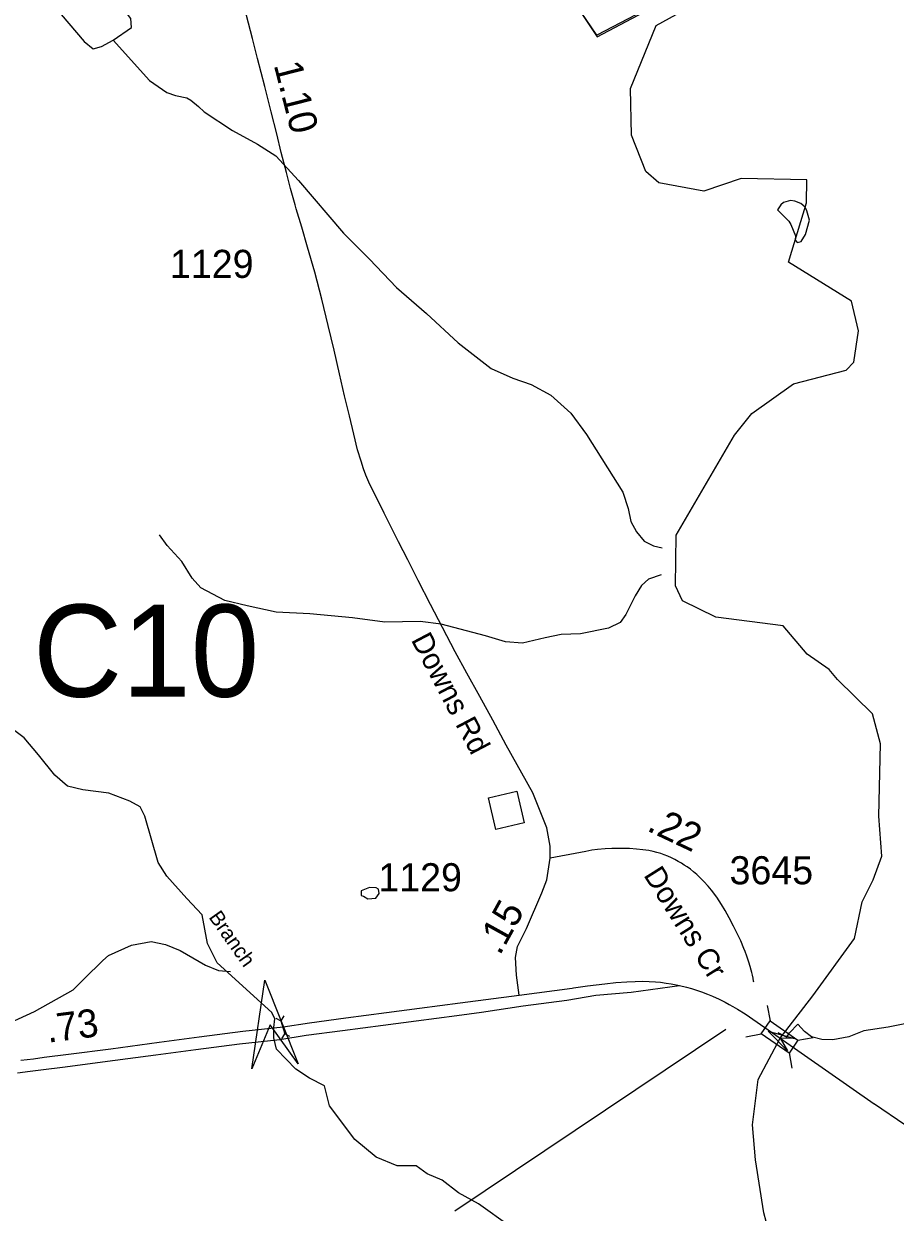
# Model space of a CAD drawing. Extents: x 1383679 to 1536984, y 460658 to 651027.
# Drawn here: x 1428508 to 1432384, y 492583 to 497871 of the extents above; entities that cross this region are included whole.
import ezdxf

# ---------------------------------------------------------------- set-up
doc = ezdxf.new("R2010")
doc.units = 0
for name, color, linetype in [('Default', 7, 'Continuous'), ('Exist Boundary Political City Limit New', 7, 'Continuous'), ('Exist Cultural Warehouse Building Footprint', 7, 'Continuous'), ('Exist Hydrographic Creek Single Shore', 7, 'Continuous'), ('Exist Hydrographic Creek Single Shore Label', 7, 'Continuous'), ('Exist Hydrographic Misc Water Feature', 7, 'Continuous'), ('Exist Road Primary NC Attributed', 7, 'Continuous'), ('Exist Road Primary NC Divided Attributed', 7, 'Continuous'), ('Exist Road Primary NC Service Mileage Hundredths English Label', 7, 'Continuous'), ('Exist Road Primary NC Structure Standard Bridge CELL', 7, 'Continuous'), ('Exist Road Secondary Mileage Hundredths English Label', 7, 'Continuous'), ('Exist Road Secondary Structure Culvert Attributed CELL', 7, 'Continuous'), ('Exist Road Secondary Structure Culvert CELL', 7, 'Continuous'), ('Exist Road Secondary Structure Culvert Number Label', 7, 'Continuous'), ('Exist Road Secondary Structure Standard Bridge Attributed CELL', 7, 'Continuous'), ('Exist Road Secondary Type 51 Attributed', 7, 'Continuous'), ('Exist Road Secondary Type 51 Label', 7, 'Continuous'), ('Exist Road Secondary Type 51 Number Label', 7, 'Continuous'), ('Map Preparation Boundary City Limit Buffer Line', 7, 'Continuous'), ('Prop Road TIP Projects U Label', 7, 'Continuous')]:
    doc.layers.add(name, color=color, linetype=linetype)

msp = doc.modelspace()

# ---------------------------------------------------------------- linework, layer by layer
at = {"layer": 'Default'}
msp.add_line((1431862.4, 493382.6), (1431901.8, 493361.5), dxfattribs=at)
msp.add_lwpolyline([(1431264.4, 497929.3), (1431056.9, 497819.8), (1430898.1, 498054.8)], dxfattribs=at)
at = {"layer": 'Exist Boundary Political City Limit New'}
for points in [[(1431264.4, 497929.3), (1431056.9, 497819.8), (1430898.1, 498054.8)], [(1430898.1, 498054.8), (1431058.5, 497813.6), (1431266, 497923.2)]]:
    msp.add_lwpolyline(points, dxfattribs=at)
at = {"layer": 'Exist Cultural Warehouse Building Footprint'}
msp.add_lwpolyline([(1430574.6, 494427.7), (1430701, 494457.2), (1430734, 494315.3), (1430607.7, 494285.9), (1430574.6, 494427.7)], dxfattribs=at)
at = {"layer": 'Exist Hydrographic Creek Single Shore'}
for points in [[(1432128, 494953), (1432090.2, 494998.4), (1431992.2, 495066), (1431886.2, 495192.9), (1431586.2, 495231.7), (1431438.3, 495303.6), (1431406.3, 495369.9), (1431410.3, 495596.3), (1431669.3, 496040.8), (1431746.3, 496137.7), (1431932.2, 496268.5), (1432166.2, 496329.5), (1432200.2, 496364.9), (1432220.2, 496505.7), (1432189.3, 496637.6), (1431909.3, 496810.6), (1431989.3, 497074.8), (1431991.2, 497176.6), (1431699.2, 497182.5), (1431532.3, 497126.7), (1431332.3, 497163.6), (1431275.3, 497214), (1431211.3, 497376.1), (1431207.3, 497583), (1431321.3, 497863), (1431498.3, 497961.2)], [(1431363.3, 491653.7), (1431867.1, 491773.5), (1431951.4, 491791.3), (1431993.6, 491822.4), (1432031.3, 491851.2), (1432031.3, 491931.1), (1432024.7, 492024.3), (1431968.2, 492141.9), (1431889.3, 492308.4), (1431841.6, 492426), (1431799.4, 492581.3), (1431762.8, 492816.6), (1431749.5, 492971.9), (1431774.4, 493174.4), (1431871.7, 493357.8), (1432018, 493546.7), (1432202.2, 493801.9), (1432237.7, 493963.9), (1432286.5, 494061.6), (1432324.2, 494168.1), (1432310.9, 494345.6), (1432318.7, 494667.4), (1432283.2, 494800.6), (1432128, 494953)], [(1430670.9, 492519.2), (1430531.1, 492621.3), (1430442.4, 492670.1), (1430369.1, 492725.6), (1430302.5, 492754.4), (1430253.7, 492789.9), (1430169.4, 492789.9), (1430076.2, 492827.7), (1429980.8, 492907.6), (1429868.2, 493057.2), (1429845.4, 493145), (1429778.8, 493180.5), (1429718.8, 493219.6), (1429632.1, 493309.4), (1429621.2, 493359.2), (1429621.2, 493404.7), (1429624.6, 493443.5), (1429611.1, 493472.6), (1429368.2, 493693.2), (1429326.1, 493779.7), (1429301.7, 493906.2), (1429232.9, 493979.4), (1429145.2, 494079.3), (1429106.4, 494139.2), (1429046.5, 494345.6), (1429026.5, 494387.8), (1428979.9, 494412.2), (1428886.7, 494447.7), (1428771.3, 494463.2), (1428702.5, 494478.8), (1428647, 494527.6), (1428573.8, 494618.6), (1428510.7, 494693.7), (1428403, 494774.9)]]:
    msp.add_lwpolyline(points, dxfattribs=at)
at = {"layer": 'Exist Hydrographic Misc Water Feature'}
for points in [[(1428906.5, 497798.4), (1428987.6, 497854.2), (1428984.4, 497894.4), (1428959, 497926.9), (1428899.4, 497947.9), (1428800.4, 497999.9), (1428747, 498035.5), (1428733.2, 498041.5), (1428683.2, 498042.5), (1428655.2, 498043.1)], [(1428655.2, 498043.1), (1428655.9, 497976.6), (1428674.6, 497912.2), (1428776.3, 497792.8), (1428817.7, 497759.9), (1428853.9, 497770.7), (1428906.5, 497798.4)], [(1428906.5, 497798.4), (1429067, 497618.7), (1429144, 497565.4), (1429183.8, 497552.4), (1429233.6, 497541.5), (1429251.5, 497531.3), (1429284.9, 497502.7), (1429310.4, 497480), (1429436.9, 497397.1), (1429547.8, 497335), (1429628.8, 497283.2), (1429730.7, 497173.7), (1429930.2, 496939.9), (1430046, 496823.5), (1430165.6, 496697.2), (1430299.4, 496582.1), (1430440.9, 496451.2), (1430586.8, 496336.7), (1430684, 496294.5), (1430765.5, 496266.6), (1430852.6, 496218.9), (1430941, 496139.2), (1431011.2, 496044.2), (1431172.2, 495786.6), (1431196.9, 495714.7), (1431207.8, 495656.2), (1431232.9, 495611.4), (1431268.1, 495568.8), (1431309.7, 495548.3), (1431347.5, 495539.3)], [(1431861.1, 497043.8), (1431910.2, 496992.8), (1431919.9, 496978.6), (1431940.9, 496928.1), (1431938.6, 496910.1), (1431948.3, 496898.5), (1431966.4, 496902.2), (1431985, 496933.8), (1432002.3, 496997.5), (1431991.1, 497039.6), (1431983.4, 497055.3), (1431963.7, 497072.1), (1431937.9, 497082.5), (1431918, 497084.5), (1431887.8, 497075.3), (1431875.6, 497065.7), (1431861.1, 497043.8)], [(1431343.2, 495419.6), (1431286.8, 495400.2), (1431256.2, 495371.3), (1431227.3, 495326), (1431185.6, 495242.3), (1431160.9, 495206.7), (1431108.4, 495181.5), (1430983.9, 495156.1), (1430897.8, 495153.7), (1430827.4, 495139.5), (1430726.9, 495115.3), (1430651.1, 495120.9), (1430561.5, 495148.1), (1430364.4, 495200.5), (1430270.6, 495212.3), (1430114.5, 495208.8), (1429970.8, 495228.2), (1429781, 495245.9), (1429631.1, 495253.1), (1429501.6, 495281.1), (1429402, 495305.3), (1429295.1, 495361.5), (1429257.9, 495404.1), (1429211.4, 495478.9), (1429146.7, 495550), (1429111.6, 495596.7)], [(1430045.3, 494027.8), (1430009, 494012.9), (1430008.6, 493992.4), (1430018.7, 493988.9), (1430038.5, 493977.9), (1430074.4, 493981.2), (1430088.9, 494001.4), (1430085.3, 494021.2), (1430075.4, 494027.2), (1430045.3, 494027.8)], [(1433299.2, 493938.4), (1433258.7, 493915.5), (1433190.4, 493900.4), (1433134.2, 493891.7), (1433118.1, 493886.3), (1433065.4, 493852.9), (1432957.5, 493757.4), (1432798.8, 493617.8), (1432650.6, 493514.9), (1432555.5, 493454.5), (1432523.2, 493441.2), (1432352.4, 493406.9), (1432244.1, 493391), (1432177.5, 493364.4), (1432107.1, 493351.1), (1432057.2, 493352.1), (1432011.4, 493363.7), (1431979.9, 493388.1), (1431950.5, 493420.7)], [(1428392.4, 493402.1), (1428555.9, 493476.8), (1428728, 493573.4), (1428776.9, 493622.5), (1428860.5, 493702.9), (1428885, 493726.1), (1428987.9, 493770.9), (1429074.3, 493787.2), (1429138.1, 493775.2), (1429203.6, 493748.4), (1429316.3, 493682.2), (1429373.9, 493658.9), (1429427.8, 493653.7)], [(1431901.8, 493361.5), (1431913.7, 493381.3), (1431950.5, 493420.7)]]:
    msp.add_lwpolyline(points, dxfattribs=at)
at = {"layer": 'Exist Road Primary NC Attributed'}
for points in [[(1431424.8, 493592.1), (1431455.1, 493585.1), (1431477.9, 493578.9), (1431499.5, 493571.7), (1431521.8, 493563.9), (1431549, 493554.1), (1431571.5, 493544.8), (1431600.5, 493530.9), (1431627.3, 493517.8), (1431645.4, 493507.7), (1431661.7, 493499), (1431682.3, 493487.1), (1431716.5, 493465.9), (1431871.7, 493357.8)], [(1431871.7, 493357.8), (1432290.7, 493066), (1432291.7, 493065.3), (1432427.3, 492973.9), (1432846.6, 492676), (1432961.4, 492591.1), (1432968.9, 492585.9), (1433416.4, 492271.8)]]:
    msp.add_lwpolyline(points, dxfattribs=at)
at = {"layer": 'Exist Road Primary NC Divided Attributed'}
for points in [[(1428480.1, 493203.8), (1428536.6, 493210.5), (1428584.3, 493216.8), (1428692.6, 493230.3), (1428880.4, 493254.7), (1429096.4, 493283.7), (1429273.4, 493307.3), (1429468.4, 493332.8), (1429647.5, 493352.5), (1429764.3, 493370.9), (1429925.7, 493392.4), (1430107.1, 493416.2), (1430253.5, 493435.4), (1430434.7, 493459.2), (1430544.4, 493473.5), (1430728.6, 493502.3), (1430923.9, 493526.7), (1431052.6, 493548.9), (1431210.2, 493562.2), (1431424.8, 493592.1)], [(1430710.9, 493548.9), (1430868.4, 493570.1), (1430947, 493580.7), (1430952.5, 493581.4), (1431015.3, 493590), (1431092.5, 493599.8), (1431141.7, 493604.8), (1431189.9, 493608.9), (1431227.6, 493610.4), (1431260.1, 493610.8), (1431289.2, 493610.4), (1431318.6, 493608.6), (1431340.6, 493606.6), (1431365.3, 493603.1), (1431387.7, 493599.4), (1431417.9, 493593.6), (1431424.8, 493592.1)], [(1428494.7, 493259.5), (1428551.1, 493266.2), (1428598.8, 493272.5), (1428707.1, 493286), (1428894.9, 493310.4), (1429110.9, 493339.4), (1429287.9, 493363), (1429482.9, 493388.4), (1429662, 493408.2), (1429778.9, 493426.6), (1429940.2, 493448.1), (1430121.7, 493471.9), (1430268, 493491.1), (1430449.2, 493514.9), (1430710.9, 493548.9)]]:
    msp.add_lwpolyline(points, dxfattribs=at)
at = {"layer": 'Exist Road Primary NC Structure Standard Bridge CELL'}
for p, q in [((1431814.5, 493502.6), (1431827.1, 493434.8)), ((1431719.3, 493364), (1431787.1, 493376.6)), ((1431951.4, 493348.9), (1432019.3, 493361.4)), ((1431912.3, 493292), (1431924.9, 493224.2))]:
    msp.add_line(p, q, dxfattribs=at)
msp.add_lwpolyline([(1431827.1, 493434.8), (1431951.6, 493349.1), (1431911.6, 493291), (1431787.1, 493376.6)], close=True, dxfattribs=at)
at = {"layer": 'Exist Road Secondary Structure Culvert Attributed CELL'}
msp.add_lwpolyline([(1429522.5, 493220.6), (1429581.1, 493616.3), (1429728.2, 493244.3), (1429604, 493417.6)], close=True, dxfattribs=at)
at = {"layer": 'Exist Road Secondary Structure Culvert CELL'}
for p, q in [((1429629.5, 493446.9), (1429652.1, 493435.4)), ((1429664.9, 493457.3), (1429652.1, 493435.4)), ((1429652.1, 493435.4), (1429669.1, 493377.3)), ((1429656.3, 493355.4), (1429669.1, 493377.3)), ((1429691.7, 493365.8), (1429669.1, 493377.3))]:
    msp.add_line(p, q, dxfattribs=at)
at = {"layer": 'Exist Road Secondary Structure Standard Bridge Attributed CELL'}
msp.add_lwpolyline([(1431904.4, 493301.6), (1431819.3, 493388.9), (1431936.6, 493355.9), (1431871.7, 493357.8)], close=True, dxfattribs=at)
at = {"layer": 'Exist Road Secondary Type 51 Attributed'}
for points in [[(1430849.6, 494159.2), (1430849.6, 494212.5), (1430835.2, 494293.5), (1430773, 494449.9), (1430653.9, 494661), (1430594.6, 494773.1), (1430536.2, 494878.5), (1430478.8, 494982.2), (1430427.3, 495077.2), (1430370.4, 495185), (1430317.1, 495288), (1430261.8, 495394.7), (1430215.9, 495486), (1430175.6, 495566.5), (1430130.6, 495655.4), (1430111.1, 495693.8), (1430069.4, 495778.2), (1430048.1, 495821.8), (1430029.7, 495863.5), (1430019.4, 495890.7), (1430008.4, 495924.5), (1429993.2, 495975.5), (1429975.8, 496045.3), (1429956.3, 496126.1), (1429935, 496215.6), (1429913, 496313.7), (1429888.4, 496418.8), (1429862.7, 496529.4), (1429833.8, 496645.4), (1429802.9, 496765.6), (1429770.3, 496876.7), (1429744.5, 496965.7), (1429719.9, 497048.1), (1429715.1, 497066), (1429695.2, 497138.9), (1429676.5, 497209.9), (1429653.8, 497298.4), (1429633.3, 497381.2), (1429608.3, 497480.1), (1429579.8, 497591.8), (1429547.7, 497716.8), (1429525.2, 497805.2), (1429490.5, 497942)], [(1431754.7, 493607.1), (1431754.3, 493610.8), (1431751.9, 493624.9), (1431749.5, 493637.4), (1431746.6, 493649.4), (1431743.3, 493660.6), (1431739.1, 493676), (1431732.8, 493695.4), (1431724.1, 493722.2), (1431716.1, 493743.5), (1431711.3, 493756.2), (1431697.1, 493790.4), (1431681.5, 493823.9), (1431665.1, 493856.7), (1431645.8, 493892.5), (1431628.1, 493925.3), (1431611.4, 493952.3), (1431589.9, 493984.7), (1431566.3, 494016.9), (1431551.5, 494034.7), (1431533.4, 494054.7), (1431518, 494070.4), (1431501.9, 494085.6), (1431487, 494098.5), (1431472.9, 494109.3), (1431459, 494119.5), (1431445.8, 494128), (1431433.9, 494135.7), (1431418.8, 494144.3), (1431403.8, 494152.7), (1431389.3, 494159.7), (1431372.3, 494167.7), (1431356.1, 494174), (1431341.7, 494178.9), (1431323.7, 494184.2), (1431307, 494188.4), (1431288.5, 494192.1), (1431261.2, 494196.3), (1431233.5, 494198.9), (1431202.2, 494201.1), (1431164.6, 494201.8), (1431123.5, 494201.4), (1431093.6, 494199.9), (1431060.1, 494197.1), (1431035.2, 494194), (1431007.5, 494188.8), (1430984.9, 494183.9), (1430849.6, 494159.2)], [(1430710.9, 493548.9), (1430699.8, 493638.8), (1430695.3, 493716.5), (1430704.2, 493765.3), (1430719.8, 493798.6), (1430744.2, 493846.3), (1430813, 494005), (1430835.2, 494062.7), (1430849.6, 494159.2)]]:
    msp.add_lwpolyline(points, dxfattribs=at)
at = {"layer": 'Map Preparation Boundary City Limit Buffer Line'}
for points in [[(1431264.4, 497929.3), (1431056.9, 497819.8), (1430898.1, 498054.8)], [(1430898.1, 498054.8), (1431058.5, 497813.6), (1431266, 497923.2)], [(1431264.4, 497929.3), (1431056.9, 497819.8), (1430898.1, 498054.8)]]:
    msp.add_lwpolyline(points, dxfattribs=at)
at = {"layer": 'Prop Road TIP Projects U Label'}
msp.add_line((1431631.4, 493396.8), (1430425, 492587.7), dxfattribs=at)

# ---------------------------------------------------------------- texts
at = {"layer": 'Exist Hydrographic Creek Single Shore Label'}
msp.add_text('Branch', height=65.62, rotation=305.2626, dxfattribs=at).set_placement((1429328.6, 493895.6))
at = {"layer": 'Exist Road Primary NC Service Mileage Hundredths English Label'}
msp.add_text('.73', height=125, rotation=7.3905, dxfattribs=at).set_placement((1428616, 493337.2))
at = {"layer": 'Exist Road Secondary Mileage Hundredths English Label'}
for s, rotation, p in [('1.10', 284.3287, (1429619.6, 497688.4)), ('.22', 334.6832, (1431274.6, 494283.1)), ('.15', 61.0232, (1430625.3, 493722))]:
    msp.add_text(s, height=125, rotation=rotation, dxfattribs=at).set_placement(p)
at = {"layer": 'Exist Road Secondary Structure Culvert Number Label'}
msp.add_text('C10', height=410.1, dxfattribs=at).set_placement((1428549.6, 494876.7))
at = {"layer": 'Exist Road Secondary Type 51 Label'}
for s, rotation, p in [('Downs Rd', 297.7585, (1430228.7, 495130.4)), ('Downs Cr', 302.2262, (1431262.5, 494083.3))]:
    msp.add_text(s, height=95, rotation=rotation, dxfattribs=at).set_placement(p)
at = {"layer": 'Exist Road Secondary Type 51 Number Label'}
for s, p in [('1129', (1429158.4, 496740.4)), ('3645', (1431647.1, 494042.4)), ('1129', (1430085.2, 494011.3))]:
    msp.add_text(s, height=125, dxfattribs=at).set_placement(p)

doc.saveas('drawing.dxf')
